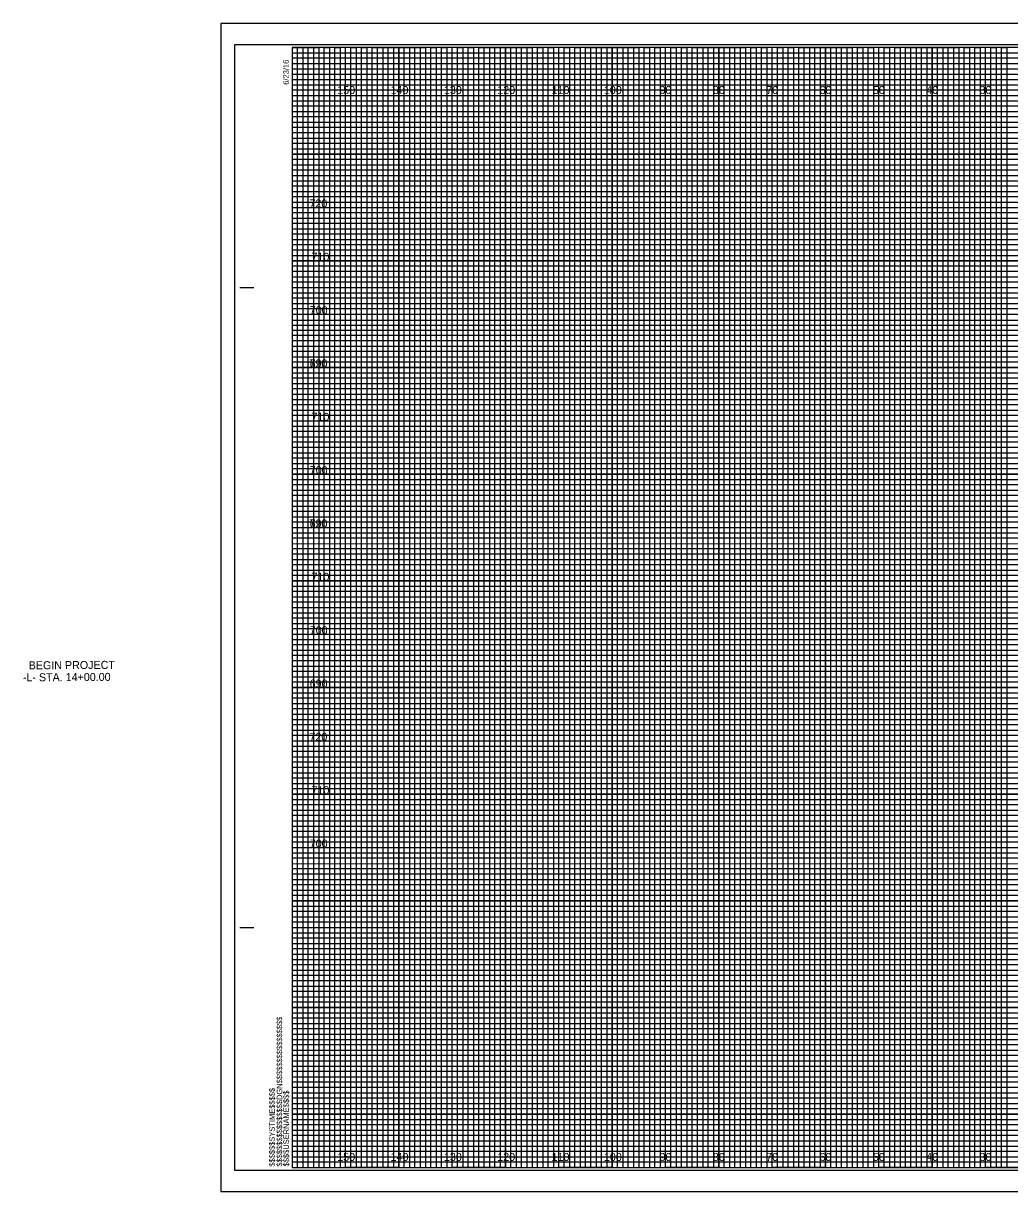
# Model space of a CAD drawing. Extents: x -98 to 717, y -10 to 1974.
# Drawn here: x -50.4 to 134.5, y 215.5 to 434.5 of the extents above; entities that cross this region are included whole.
import ezdxf

# ---------------------------------------------------------------- set-up
doc = ezdxf.new("R2010")
doc.units = 0
for name, color, linetype in [('Exist XS Center Line Elevation Label', 7, 'Continuous'), ('Prop CMT Conc Surface', 7, 'Continuous'), ('Prop CMT Concrete Structures', 7, 'Continuous'), ('Prop CMT Pvmt Course 1 CG', 7, 'Continuous'), ('Prop CMT Pvmt Course 2', 7, 'Continuous'), ('Prop CMT Pvmt Course 3', 7, 'Continuous'), ('Prop CMT Pvmt Surface', 7, 'Continuous'), ('Prop CMT Subgrade Earthwork', 7, 'Continuous'), ('Prop XS Dump Level', 7, 'Continuous'), ('Prop XS Earthwork Shape', 7, 'Continuous'), ('Prop XS Elevation Labels', 7, 'Continuous'), ('Typical Curb CELL', 7, 'Continuous')]:
    doc.layers.add(name, color=color, linetype=linetype)

msp = doc.modelspace()

# ---------------------------------------------------------------- linework, layer by layer
at = {"layer": 'Exist XS Center Line Elevation Label'}
for p, q in [((0, 429), (260, 429)), ((260, 427.98), (0, 427.98)), ((0, 427.98), (0, 427)), ((0, 427), (260, 427)), ((260, 425.89), (0, 425.89)), ((0, 425.89), (0, 424)), ((0, 424), (320, 424))]:
    msp.add_line(p, q, dxfattribs=at)
for points in [[(0, 423), (270, 423), (320, 423), (320, 422), (0, 422)], [(0, 421), (320, 421), (320, 419), (0, 419)], [(0, 418), (320, 418), (320, 417), (0, 416.98)], [(0, 416), (320, 416), (320, 414), (0, 414)], [(0, 413), (320, 413), (320, 412), (0, 412)], [(0, 411), (320, 411), (320, 409), (0, 409)], [(0, 408), (320, 408), (320, 407), (0, 407)], [(0, 406), (320, 406), (320, 404), (0, 404)], [(0, 403), (320, 403), (320, 402), (0, 402)], [(0, 401), (320, 401), (320, 399), (0, 399)], [(0, 398), (320, 398), (320, 397), (0, 397)], [(0, 396), (320, 396), (320, 393.95), (320, 393), (320, 392), (0, 392)], [(0, 394), (320, 394), (320, 393), (0, 393)], [(0, 391), (320, 391), (320, 389), (0, 389.03)], [(0, 389.03), (320, 389), (320, 388), (0, 388)], [(0, 387), (320, 387), (320, 386), (0, 386)], [(0, 384), (320, 384), (320, 383), (0, 383)], [(0, 382), (320, 382), (320, 381), (0, 381)], [(-0.07, 378.89), (320, 378.89), (320, 377.88), (-0.07, 377.88)], [(0, 377), (320, 377), (320, 376), (0, 376)], [(0, 374), (320, 374), (320, 373), (0, 373)], [(0, 372), (320, 372), (320, 371), (0, 371)], [(0, 369), (320, 369), (320, 368), (0, 368)], [(0, 367), (320, 367), (320, 366), (0, 366)], [(0, 364), (320, 364), (320, 363), (0, 363)], [(0, 362), (320, 362), (320, 361), (0, 361)], [(0, 359), (320, 359), (319.99, 357.98), (0, 358)], [(0, 357), (320, 357), (320, 356), (0, 356)], [(0, 354), (320, 354), (320, 353), (0, 353)], [(0, 352), (320, 352), (320, 351), (0, 351)], [(0, 349), (320, 349), (320, 348), (0, 348)], [(0, 347), (320, 347), (320, 346), (0, 346)], [(0, 344), (320, 344), (320, 343), (0, 343)], [(0, 342), (320, 342), (320, 341), (0, 341)], [(0, 339), (320, 339), (320, 338), (0, 338)], [(0, 336.99), (320.07, 336.91), (320, 336), (0, 336)], [(0, 334), (320, 334), (320, 333), (0, 333)], [(0, 332), (320, 332), (320, 331), (0, 331)], [(0, 329), (320, 329), (320, 328), (0, 328)], [(0, 327), (320, 327), (320, 326), (0, 326)], [(0, 324), (320, 324), (320, 323), (0, 323)], [(0, 322), (320, 322), (320, 321), (0, 321)], [(0, 319), (320, 319), (320, 318), (0, 318)], [(0, 317), (320, 317), (320, 316), (0, 316)], [(0, 314), (320, 314), (320, 313), (0, 313)], [(0, 312), (320, 312), (320, 311), (0, 311)], [(0, 309), (320, 309), (320, 308), (0, 308)], [(0, 307), (320, 307), (320, 306), (0, 306)], [(0, 304), (320, 304), (320, 303), (0, 303)], [(0, 302), (320, 302), (320, 301), (0, 301)], [(0, 299), (320, 299), (319.99, 297.98), (0, 298)], [(0, 297), (320, 297), (320, 296), (0, 296)], [(0, 294), (320, 294), (320, 293), (0, 293)], [(0, 292), (320, 292), (320, 291), (0, 291)], [(0, 289), (320, 289), (320, 288), (0, 288)], [(0, 287), (320, 287), (320, 286), (0, 286)], [(0, 284), (320, 284), (320, 283), (0, 283)], [(0, 282), (320, 282), (320, 281), (0, 281)], [(0, 279), (320, 279), (320, 278), (0, 278)], [(0, 276.99), (320.07, 276.91), (320, 276), (0, 276)], [(0, 274), (320, 274), (320, 273), (0, 273)], [(0, 272), (320, 272), (320, 271), (0, 271)], [(0, 269), (320, 269), (320, 268), (0, 268)], [(0, 267), (320, 267), (320, 266), (0, 266)], [(0, 264), (320, 264), (320, 263), (0, 263)], [(0, 262), (320, 262), (320, 261), (0, 261)], [(0, 259), (320, 259), (320, 258), (0, 258)], [(0, 257), (320, 257), (320, 256), (0, 256)], [(0, 254), (320, 254), (320, 253), (0, 253)], [(0, 252), (320, 252), (320, 251), (0, 251)], [(0, 249), (320, 249), (320, 248), (0, 248)], [(0, 247), (320, 247), (320, 246), (0, 246)], [(0, 244), (320, 244), (320, 243), (0, 243)], [(0, 242), (320, 242), (320, 241), (0, 241)], [(0, 239), (320, 239), (320, 238), (0, 238)], [(0, 237), (320, 237), (320, 236), (0, 236)], [(0, 234), (320, 234), (320, 233), (0, 233)], [(0, 232), (320, 232), (320, 231), (0, 231)], [(0, 229), (320, 229), (320, 228), (0, 228)], [(0, 227), (320, 227), (320, 226), (0, 226)], [(0, 224), (320, 224), (320, 223), (0, 223)], [(0, 222), (320, 222), (320, 221), (0, 221)]]:
    msp.add_lwpolyline(points, dxfattribs=at)
at = {"layer": 'Prop CMT Conc Surface'}
for p, q in [((-9.8, 385), (-7.3, 385)), ((-9.7, 385), (-7.2, 385)), ((-9.8, 265), (-7.3, 265)), ((-9.7, 265), (-7.2, 265)), ((0, 220), (0, 220)), ((0, 220), (0, 220)), ((0, 220), (0, 220)), ((0, 220), (0, 220)), ((0, 220), (0, 220)), ((0, 220), (0, 220)), ((0, 220), (0, 220))]:
    msp.add_line(p, q, dxfattribs=at)
msp.add_lwpolyline([(320, 430), (0, 430), (0, 220), (320, 220)], close=True, dxfattribs=at)
at = {"layer": 'Prop CMT Concrete Structures'}
for p, q in [((10, 220), (10, 430)), ((20, 220), (20, 430)), ((30, 220), (30, 430)), ((40, 220), (40, 430)), ((50, 220), (50, 430)), ((60, 220), (60, 430)), ((70, 220), (70, 430)), ((80, 220), (80, 430)), ((90, 220), (90, 430)), ((100, 220), (100, 430)), ((110, 220), (110, 430)), ((120, 220), (120, 430)), ((130, 220), (130, 430)), ((0, 420), (320, 420)), ((0, 410), (320, 410)), ((0, 400), (320, 400)), ((0, 390), (320, 390)), ((0, 380), (320, 380)), ((0, 370), (320, 370)), ((0, 360), (320, 360)), ((0, 350), (320, 350)), ((0, 340), (320, 340)), ((0, 330), (320, 330)), ((0, 320), (320, 320)), ((0, 310), (320, 310)), ((0, 300), (320, 300)), ((0, 290), (320, 290)), ((0, 280), (320, 280)), ((0, 270), (320, 270)), ((0, 260), (320, 260)), ((0, 250), (320, 250)), ((0, 240), (320, 240)), ((0, 230), (320, 230))]:
    msp.add_line(p, q, dxfattribs=at)
at = {"layer": 'Prop CMT Pvmt Course 2'}
msp.add_lwpolyline([(-13.4, 215.5), (323.3, 215.5), (323.3, 434.5), (-13.4, 434.5)], close=True, dxfattribs=at)
at = {"layer": 'Prop CMT Pvmt Course 3'}
msp.add_lwpolyline([(-10.8, 219.5), (322.4, 219.5), (322.4, 430.5), (-10.8, 430.5)], close=True, dxfattribs=at)
at = {"layer": 'Prop CMT Pvmt Surface'}
for p, q in [((323.3, 434.5), (-13.4, 434.5)), ((-13.4, 434.5), (-13.4, 215.5)), ((-13.4, 215.5), (323.3, 215.5))]:
    msp.add_line(p, q, dxfattribs=at)
at = {"layer": 'Prop CMT Subgrade Earthwork'}
for points in [[(0, 220), (1, 220), (1, 430), (2, 430), (2, 220)], [(2, 220), (3, 220), (3, 430), (4, 430), (4, 220)], [(5, 220), (6, 220), (6, 430), (7, 430), (7, 220)], [(7, 220), (8, 220), (8, 430), (9, 430), (9, 220)], [(10, 220), (11, 220), (11, 430), (12, 430), (12, 220)], [(12, 220), (13, 220), (13, 430), (14, 430), (14, 220)], [(15, 220), (16, 220), (16, 430), (17, 430), (17, 220)], [(17, 220), (18, 220), (18, 430), (19, 430), (19, 220)], [(20, 220), (21, 220), (21, 430), (22, 430), (22, 220)], [(22, 220), (23, 220), (23, 430), (24, 430), (24, 220)], [(25, 220), (26, 220), (26, 430), (27, 430), (27, 220)], [(27, 220), (28, 220), (28, 430), (29, 430), (29, 220)], [(30, 220), (31, 220), (31, 430), (32, 430), (32, 220)], [(32, 220), (33, 220), (33, 430), (34, 430), (34, 220)], [(35, 220), (36, 220), (36, 430), (37, 430), (37, 220)], [(37, 220), (38, 220), (38, 430), (39, 430), (39, 220)], [(40, 220), (41, 220), (41, 430), (42, 430), (42, 220)], [(42, 220), (43, 220), (43, 430), (44, 430), (44, 220)], [(45, 220), (46, 220), (46, 430), (47, 430), (47, 220)], [(47, 220), (48, 220), (48, 430), (49, 430), (49, 220)], [(50, 220), (51, 220), (51, 430), (52, 430), (52, 220)], [(52, 220), (53, 220), (53, 430), (54, 430), (54, 220)], [(55, 220), (56, 220), (56, 430), (57, 430), (57, 220)], [(57, 220), (58, 220), (58, 430), (59, 430), (59, 220)], [(60, 220), (61, 220), (61, 430), (62, 430), (62, 220)], [(62, 220), (63, 220), (63, 430), (64, 430), (64, 220)], [(65, 220), (66, 220), (66, 430), (67, 430), (67, 220)], [(67, 220), (68, 220), (68, 430), (69, 430), (69, 220)], [(70, 220), (71, 220), (71, 430), (72, 430), (72, 220)], [(72, 220), (73, 220), (73, 430), (74, 430), (74, 220)], [(75, 220), (76, 220), (76, 430), (77, 430), (77, 220)], [(77, 220), (78, 220), (78, 430), (79, 430), (79, 220)], [(80, 220), (81, 220), (81, 430), (82, 430), (82, 220)], [(82, 220), (83, 220), (83, 430), (84, 430), (84, 220)], [(85, 220), (86, 220), (86, 430), (87, 430), (87, 220)], [(87, 220), (88, 220), (88, 430), (89, 430), (89, 220)], [(90, 220), (91, 220), (91, 430), (92, 430), (92, 220)], [(92, 220), (93, 220), (93, 430), (94, 430), (94, 220)], [(95, 220), (96, 220), (96, 430), (97, 430), (97, 220)], [(97, 220), (98, 220), (98, 430), (99, 430), (99, 220)], [(100, 220), (101, 220), (101, 430), (102, 430), (102, 220)], [(102, 220), (103, 220), (103, 430), (104, 430), (104, 220)], [(105, 220), (106, 220), (106, 430), (107, 430), (107, 220)], [(107, 220), (108, 220), (108, 430), (109, 430), (109, 220)], [(110, 220), (111, 220), (111, 430), (112, 430), (112, 220)], [(112, 220), (113, 220), (113, 430), (114, 430), (114, 220)], [(115, 220), (116, 220), (116, 430), (117, 430), (117, 220)], [(117, 220), (118, 220), (118, 430), (119, 430), (119, 220)], [(120, 220), (121, 220), (121, 430), (122, 430), (122, 220)], [(122, 220), (123, 220), (123, 430), (124, 430), (124, 220)], [(125, 220), (126, 220), (126, 430), (127, 430), (127, 220)], [(127, 220), (128, 220), (128, 430), (129, 430), (129, 220)], [(130, 220), (131, 220), (131, 430), (132, 430), (132, 220)], [(132, 220), (133, 220), (133, 430), (134, 430), (134, 220)]]:
    msp.add_lwpolyline(points, dxfattribs=at)
at = {"layer": 'Prop XS Elevation Labels'}
for p, q in [((10, 430), (0, 430)), ((10, 220), (10, 430)), ((30, 430), (20, 430)), ((20, 430), (20, 220)), ((30, 220), (30, 430)), ((50, 430), (40, 430)), ((40, 430), (40, 220)), ((50, 220), (50, 430)), ((70, 430), (60, 430)), ((60, 430), (60, 220)), ((70, 220), (70, 430)), ((90, 430), (80, 430)), ((80, 430), (80, 220)), ((90, 220), (90, 430)), ((110, 430), (100, 430)), ((100, 430), (100, 220)), ((110, 220), (110, 430)), ((130, 430), (120, 430)), ((120, 430), (120, 220)), ((130, 220), (130, 430)), ((20, 220), (10, 220)), ((40, 220), (30, 220)), ((60, 220), (50, 220)), ((80, 220), (70, 220)), ((100, 220), (90, 220)), ((120, 220), (110, 220)), ((140, 220), (130, 220))]:
    msp.add_line(p, q, dxfattribs=at)
for points in [[(0, 420), (320, 420), (320, 410), (0, 410)], [(0, 400), (320, 400), (320, 390), (0, 390)], [(0, 380), (320, 380), (320, 370), (0, 370)], [(0, 360), (320, 360), (320, 350), (0, 350)], [(0, 340), (320, 340), (320, 330), (0, 330)], [(0, 320), (320, 320), (320, 310), (0, 310)], [(0, 300), (320, 300), (320, 290), (0, 290)], [(0, 280), (320, 280), (320, 270), (0, 270)], [(0, 260), (320, 260), (320, 250), (0, 250)], [(0, 240), (320, 240), (320, 230), (0, 230)]]:
    msp.add_lwpolyline(points, dxfattribs=at)
at = {"layer": 'Typical Curb CELL'}
for points in [[(0, 430), (5, 430), (5, 220), (15, 220), (15, 430), (25, 430), (25, 220), (35, 220), (35, 430), (45, 430), (45, 220), (55, 220), (55, 430), (65, 430), (65, 220), (75, 220), (75, 430), (85, 430), (85, 220), (95, 220), (95, 430), (105, 430), (105, 220), (115, 220), (115, 430), (125, 430), (125, 220), (135, 220)], [(0, 425), (275, 425)], [(0, 405), (320, 405), (320, 415), (0, 415)], [(0, 385), (320, 385), (320, 395), (0, 395)], [(0, 365), (320, 365), (320, 375), (0, 375)], [(0, 345), (320, 345), (320, 355), (0, 355)], [(0, 325), (320, 325), (320, 335), (0, 335)], [(0, 305), (320, 305), (320, 315), (0, 315)], [(0, 285), (320, 285), (320, 295), (0, 295)], [(0, 265), (320, 265), (320, 275), (0, 275)], [(0, 245), (320, 245), (320, 255), (0, 255)], [(0, 225), (320, 225), (320, 235), (0, 235)]]:
    msp.add_lwpolyline(points, dxfattribs=at)

# ---------------------------------------------------------------- texts
at = {"layer": 'Prop CMT Conc Surface'}
for s, p in [('6/23/16', (-0.65, 423)), ('$$$$$$$$$$$$$$$$DGN$$$$$$$$$$$$$$$$', (-1.88, 220.18)), ('$$$$$$SYSTIME$$$$$', (-3.26, 220.18)), ('$$$$USERNAME$$$$', (-0.62, 220.23))]:
    msp.add_text(s, height=1.05, rotation=90, dxfattribs=at).set_placement(p)
at = {"layer": 'Prop CMT Pvmt Course 1 CG'}
for s, p in [('720', (3.23, 400)), ('710', (3.61, 390)), ('700', (3.28, 380)), ('720', (3.23, 370)), ('690', (3.26, 370)), ('710', (3.61, 360)), ('700', (3.28, 350)), ('720', (3.23, 340)), ('690', (3.26, 340)), ('710', (3.61, 330)), ('700', (3.28, 320)), ('690', (3.26, 310)), ('720', (3.23, 300)), ('710', (3.61, 290)), ('700', (3.28, 280))]:
    msp.add_text(s, height=1.5, dxfattribs=at).set_placement(p)
at = {"layer": 'Prop XS Dump Level'}
for s, p in [('BEGIN PROJECT', (-49.41, 313.41)), ('-L- STA. 14+00.00', (-50.5, 311.15))]:
    msp.add_text(s, height=1.5, rotation=0.3249, dxfattribs=at).set_placement(p)
at = {"layer": 'Prop XS Earthwork Shape'}
for s, p in [('150', (8.44, 421.25)), ('140', (18.44, 421.25)), ('130', (28.44, 421.25)), ('120', (38.44, 421.25)), ('110', (48.62, 421.25)), ('100', (58.44, 421.25)), ('90', (68.86, 421.25)), ('80', (78.86, 421.25)), ('70', (88.86, 421.25)), ('60', (98.86, 421.25)), ('50', (108.86, 421.25)), ('40', (118.86, 421.25)), ('30', (128.86, 421.25)), ('150', (8.44, 221.25)), ('140', (18.44, 221.25)), ('130', (28.44, 221.25)), ('120', (38.44, 221.25)), ('110', (48.62, 221.25)), ('100', (58.44, 221.25)), ('90', (68.86, 221.25)), ('80', (78.86, 221.25)), ('70', (88.86, 221.25)), ('60', (98.86, 221.25)), ('50', (108.86, 221.25)), ('40', (118.86, 221.25)), ('30', (128.86, 221.25))]:
    msp.add_text(s, height=1.5, dxfattribs=at).set_placement(p)

doc.saveas('drawing.dxf')
